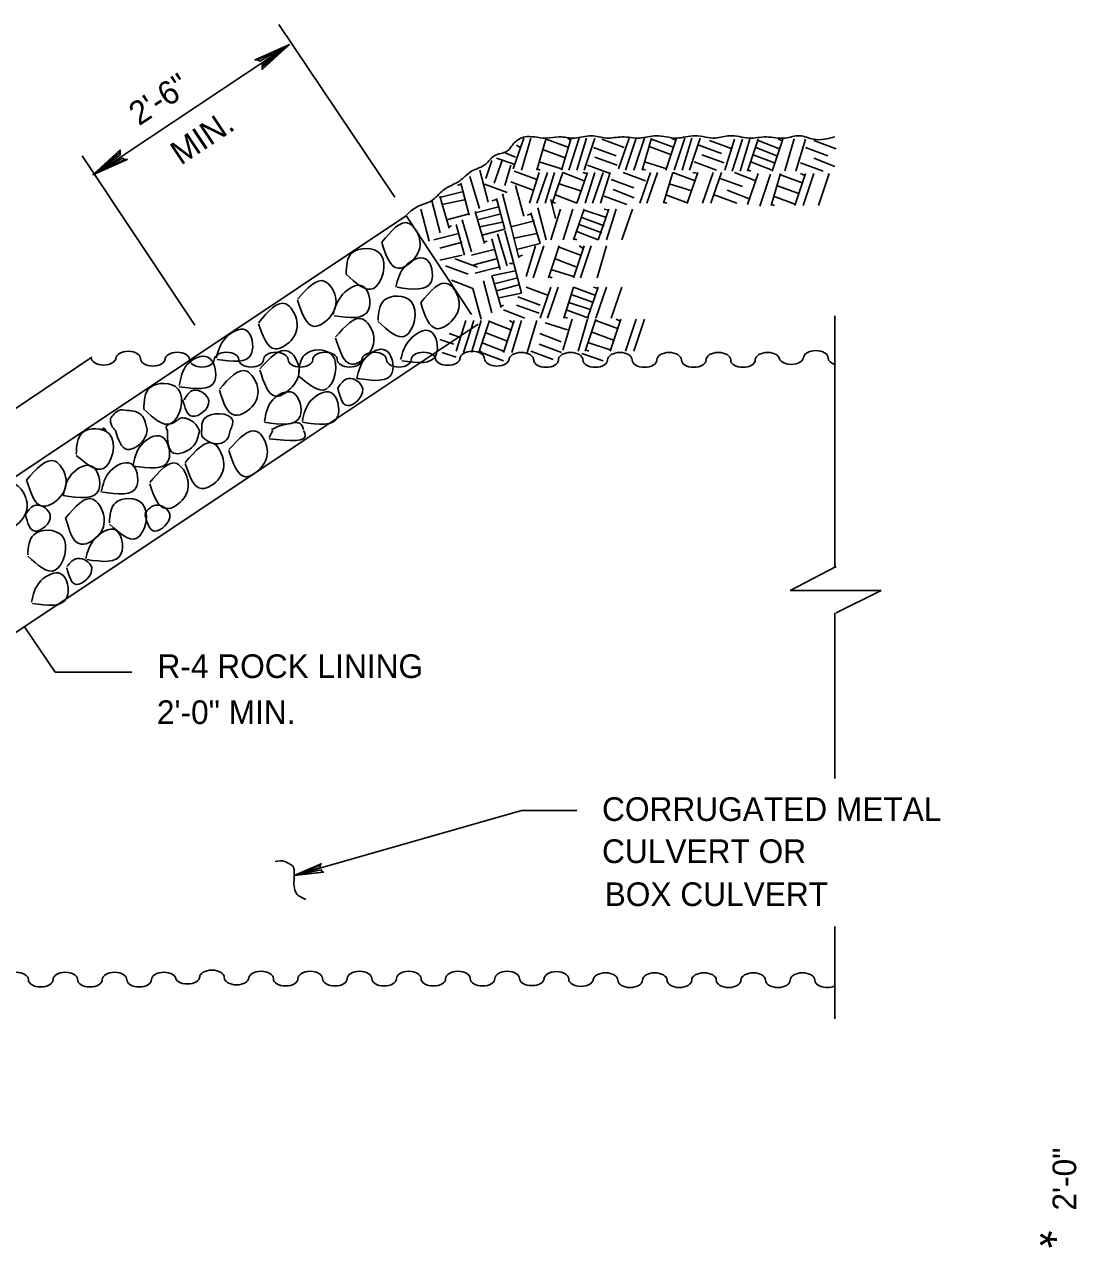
# Model space of a CAD drawing. Extents: x 639011 to 639866, y 298840 to 300028.
# Drawn here: x 639264.7 to 639398.1, y 298970.3 to 299125.2 of the extents above; entities that cross this region are included whole.
import ezdxf

# ---------------------------------------------------------------- set-up
doc = ezdxf.new("R2010")
doc.units = 0
doc.layers.add('2', color=7, linetype='Continuous')

msp = doc.modelspace()

# ---------------------------------------------------------------- linework, layer by layer
at = {"layer": '2'}
for p, q in [((639311.64, 299103.35), (639296.94, 299125.25)), ((639273.61, 299106.24), (639298.29, 299122.7)), ((639327.99, 299110.85), (639326.64, 299106.95)), ((639328.89, 299110.85), (639327.69, 299106.8)), ((639330.84, 299110.85), (639329.64, 299106.8)), ((639333.69, 299109.65), (639330.84, 299110.7)), ((639333.99, 299110.85), (639332.79, 299106.8)), ((639333.99, 299110.55), (639333.54, 299110.85)), ((639335.04, 299110.85), (639333.69, 299106.8)), ((639335.94, 299110.85), (639334.74, 299106.8)), ((639336.99, 299110.85), (639335.64, 299106.8)), ((639340.74, 299109.65), (639337.89, 299110.7)), ((639341.34, 299110.85), (639339.99, 299106.95)), ((639342.24, 299110.85), (639340.89, 299106.8)), ((639343.29, 299110.85), (639341.94, 299106.8)), ((639344.19, 299110.85), (639342.99, 299106.8)), ((639347.04, 299109.65), (639344.19, 299110.7)), ((639347.34, 299110.85), (639345.99, 299106.8)), ((639347.34, 299110.55), (639346.74, 299110.85)), ((639348.39, 299110.85), (639347.04, 299106.8)), ((639349.29, 299110.85), (639348.09, 299106.8)), ((639350.34, 299110.85), (639348.99, 299106.8)), ((639354.39, 299109.5), (639351.54, 299110.55)), ((639354.69, 299110.7), (639353.49, 299106.8)), ((639355.74, 299110.7), (639354.39, 299106.65)), ((639356.64, 299110.7), (639355.44, 299106.65)), ((639357.69, 299110.7), (639356.34, 299106.65)), ((639360.39, 299109.5), (639357.69, 299110.55)), ((639360.84, 299110.7), (639359.49, 299106.65)), ((639360.69, 299110.55), (639360.24, 299110.7)), ((639362.28, 299110.77), (639361.08, 299106.72)), ((639363.69, 299110.7), (639362.49, 299106.65)), ((639367.59, 299109.5), (639364.74, 299110.55)), ((639286.29, 299087.15), (639272.04, 299108.6)), ((639326.94, 299108.45), (639325.44, 299109.05)), ((639327.54, 299109.65), (639327.09, 299109.95)), ((639333.24, 299108.36), (639330.39, 299109.41)), ((639339.69, 299108.6), (639336.84, 299109.65)), ((639346.74, 299108.75), (639343.89, 299109.8)), ((639353.04, 299108.9), (639350.19, 299109.95)), ((639353.4, 299107.7), (639350.55, 299108.75)), ((639359.79, 299107.7), (639357.09, 299108.75)), ((639360.09, 299108.6), (639357.39, 299109.65)), ((639366.54, 299108.6), (639363.69, 299109.65)), ((639323.94, 299108), (639323.19, 299105.75)), ((639325.29, 299108.15), (639324.24, 299105.15)), ((639326.79, 299107.55), (639324.54, 299108.3)), ((639326.34, 299107.4), (639325.59, 299104.85)), ((639332.79, 299106.95), (639329.94, 299107.85)), ((639338.94, 299106.35), (639336.09, 299107.4)), ((639339.84, 299107.4), (639336.99, 299108.45)), ((639346.14, 299106.95), (639343.29, 299107.85)), ((639352.44, 299106.8), (639349.59, 299107.85)), ((639359.49, 299106.8), (639356.79, 299107.85)), ((639365.94, 299106.65), (639363.09, 299107.7)), ((639367.44, 299107.25), (639364.74, 299108.3)), ((639321.18, 299105.98), (639322.38, 299101.93)), ((639322.44, 299106.8), (639323.49, 299102.75)), ((639329.64, 299105.6), (639326.79, 299106.65)), ((639329.94, 299106.5), (639328.74, 299102.6)), ((639330.09, 299106.8), (639329.64, 299106.95)), ((639330.99, 299106.5), (639329.64, 299102.6)), ((639331.89, 299106.5), (639330.69, 299102.6)), ((639332.94, 299106.5), (639331.59, 299102.6)), ((639335.64, 299105.45), (639332.94, 299106.5)), ((639336.09, 299106.5), (639334.74, 299102.6)), ((639335.94, 299106.35), (639335.49, 299106.5)), ((639336.99, 299106.5), (639335.79, 299102.6)), ((639338.04, 299106.5), (639336.69, 299102.6)), ((639338.94, 299106.5), (639337.74, 299102.6)), ((639341.94, 299104.55), (639339.09, 299105.6)), ((639343.44, 299105.45), (639340.59, 299106.5)), ((639344.04, 299106.5), (639342.69, 299102.6)), ((639343.44, 299106.8), (639342.99, 299106.95)), ((639344.94, 299106.5), (639343.59, 299102.6)), ((639346.89, 299106.5), (639345.69, 299102.6)), ((639349.74, 299105.45), (639346.89, 299106.5)), ((639350.04, 299106.5), (639348.69, 299102.6)), ((639350.04, 299106.35), (639349.44, 299106.5)), ((639351.99, 299106.5), (639350.64, 299102.6)), ((639353.04, 299106.5), (639351.69, 299102.6)), ((639355.74, 299104.7), (639352.89, 299105.75)), ((639357.39, 299105.45), (639354.69, 299106.5)), ((639357.69, 299106.35), (639356.34, 299102.45)), ((639356.79, 299106.65), (639356.49, 299106.8)), ((639359.25, 299106.27), (639357.9, 299102.22)), ((639360.54, 299106.35), (639359.34, 299102.3)), ((639363.39, 299105.15), (639360.54, 299106.2)), ((639363.69, 299106.35), (639362.34, 299102.3)), ((639363.69, 299106.05), (639363.09, 299106.35)), ((639364.74, 299106.35), (639363.39, 299102.3)), ((639366.69, 299106.35), (639365.34, 299102.3)), ((639320.34, 299104.1), (639317.49, 299103.35)), ((639320.04, 299105), (639319.59, 299104.85)), ((639320.04, 299105.15), (639321.09, 299101.1)), ((639325.89, 299103.95), (639323.04, 299105)), ((639329.19, 299104.25), (639326.34, 299105.3)), ((639326.94, 299104.85), (639327.99, 299100.95)), ((639335.19, 299104.16), (639332.49, 299105.06)), ((639342.01, 299103.28), (639339.31, 299104.33)), ((639349.29, 299104.16), (639346.44, 299105.06)), ((639356.49, 299103.2), (639353.79, 299104.25)), ((639362.87, 299103.81), (639360.02, 299104.86)), ((639316.36, 299102.9), (639317.41, 299098.85)), ((639317.34, 299103.5), (639318.54, 299099.45)), ((639320.64, 299103.05), (639317.64, 299102.45)), ((639324.54, 299103.05), (639323.94, 299102.9)), ((639324.54, 299103.2), (639325.59, 299099.3)), ((639325.29, 299103.8), (639326.34, 299099.75)), ((639331.44, 299103.05), (639332.04, 299100.65)), ((639332.04, 299102.6), (639331.74, 299102.75)), ((639334.74, 299102.6), (639332.04, 299103.65)), ((639341.04, 299102.45), (639338.19, 299103.5)), ((639346.14, 299102.6), (639345.69, 299102.75)), ((639348.84, 299102.6), (639345.99, 299103.65)), ((639354.99, 299102.6), (639352.14, 299103.65)), ((639359.79, 299102.3), (639359.34, 299102.45)), ((639362.49, 299102.45), (639359.64, 299103.5)), ((639272.34, 299073.8), (639312.99, 299100.95)), ((639321.39, 299088.5), (639313.14, 299100.95)), ((639314.94, 299101.85), (639315.99, 299097.8)), ((639321.09, 299101.25), (639318.24, 299100.5)), ((639324.84, 299102.15), (639321.84, 299101.4)), ((639321.84, 299101.55), (639323.04, 299097.5)), ((639325.14, 299101.25), (639322.14, 299100.5)), ((639329.04, 299101.25), (639328.44, 299101.1)), ((639328.89, 299101.4), (639330.09, 299097.5)), ((639329.79, 299102), (639330.84, 299097.95)), ((639332.64, 299101.85), (639331.44, 299097.95)), ((639334.2, 299101.85), (639333, 299097.95)), ((639335.64, 299101.85), (639334.29, 299097.95)), ((639338.19, 299099.75), (639335.34, 299100.8)), ((639338.49, 299100.8), (639335.64, 299101.7)), ((639338.79, 299101.85), (639337.44, 299097.95)), ((639338.79, 299101.7), (639338.19, 299101.85)), ((639339.69, 299101.85), (639338.49, 299097.95)), ((639341.79, 299101.85), (639340.44, 299097.95)), ((639318.84, 299099.75), (639318.54, 299099.6)), ((639319.44, 299099.9), (639320.49, 299096)), ((639320.19, 299100.5), (639321.39, 299096.45)), ((639325.29, 299100.2), (639322.44, 299099.6)), ((639325.59, 299099.3), (639322.74, 299098.55)), ((639329.34, 299100.35), (639326.34, 299099.6)), ((639326.34, 299099.75), (639327.39, 299095.7)), ((639337.89, 299098.85), (639335.04, 299099.9)), ((639319.59, 299098.7), (639316.59, 299097.95)), ((639323.34, 299097.8), (639322.89, 299097.65)), ((639323.94, 299098.1), (639324.99, 299094.2)), ((639324.69, 299098.7), (639325.89, 299094.65)), ((639325.59, 299099.15), (639326.64, 299095.25)), ((639329.64, 299098.78), (639326.79, 299098.18)), ((639334.74, 299097.95), (639334.44, 299098.1)), ((639337.44, 299097.95), (639334.74, 299099)), ((639320.19, 299097.65), (639317.34, 299096.9)), ((639324.24, 299096.75), (639321.39, 299096)), ((639330.09, 299097.5), (639327.09, 299096.75)), ((639329.49, 299097.2), (639328.29, 299093.3)), ((639330.54, 299097.2), (639329.19, 299093.15)), ((639332.49, 299097.2), (639331.14, 299093.15)), ((639335.19, 299096), (639332.49, 299097.05)), ((639335.64, 299097.2), (639334.29, 299093.15)), ((639335.49, 299096.9), (639335.04, 299097.2)), ((639336.54, 299097.2), (639335.19, 299093.15)), ((639338.49, 299097.2), (639337.29, 299093.15)), ((639320.19, 299096), (639317.34, 299095.4)), ((639320.94, 299093.6), (639318.09, 299094.65)), ((639322.14, 299094.5), (639319.29, 299095.55)), ((639324.54, 299095.55), (639321.69, 299094.8)), ((639326.64, 299094.95), (639326.19, 299094.95)), ((639326.64, 299095.25), (639327.69, 299091.2)), ((639327.84, 299096), (639327.39, 299095.85)), ((639334.58, 299094.56), (639331.88, 299095.61)), ((639324.84, 299094.5), (639321.84, 299093.75)), ((639323.94, 299093.45), (639325.14, 299089.4)), ((639326.94, 299094.05), (639324.09, 299093.45)), ((639327.24, 299093.15), (639324.24, 299092.4)), ((639331.59, 299093.15), (639331.14, 299093.3)), ((639334.29, 299093.3), (639331.44, 299094.2)), ((639321.54, 299091.8), (639318.84, 299092.85)), ((639321.54, 299091.8), (639322.59, 299087.9)), ((639322.88, 299092.77), (639323.93, 299088.72)), ((639327.39, 299092.25), (639324.54, 299091.5)), ((639331.14, 299090.9), (639328.29, 299091.95)), ((639331.44, 299091.95), (639330.09, 299088.05)), ((639332.34, 299091.95), (639330.99, 299088.05)), ((639334.29, 299091.95), (639333.09, 299088.05)), ((639337.14, 299090.9), (639334.29, 299091.95)), ((639337.44, 299091.95), (639336.09, 299088.05)), ((639337.44, 299091.8), (639336.84, 299091.95)), ((639338.49, 299091.95), (639337.14, 299088.05)), ((639340.44, 299091.95), (639339.09, 299088.05)), ((639327.69, 299091.2), (639324.84, 299090.6)), ((639330.09, 299089.7), (639327.24, 299090.75)), ((639336.54, 299089.1), (639333.69, 299090)), ((639336.84, 299090), (639333.99, 299091.05)), ((639325.44, 299089.7), (639325.14, 299089.55)), ((639328.14, 299088.05), (639325.44, 299089.1)), ((639329.94, 299088.65), (639327.09, 299089.7)), ((639336.24, 299088.05), (639333.39, 299089.1)), ((639300.15, 299072.58), (639322.2, 299087.28)), ((639320.64, 299087.75), (639319.44, 299083.85)), ((639321.69, 299087.75), (639320.34, 299083.7)), ((639322.59, 299087.75), (639321.39, 299083.7)), ((639323.64, 299087.75), (639322.29, 299083.7)), ((639326.34, 299086.55), (639323.64, 299087.6)), ((639326.79, 299087.75), (639325.44, 299083.7)), ((639326.64, 299087.45), (639326.19, 299087.75)), ((639327.69, 299087.75), (639326.49, 299083.7)), ((639329.64, 299087.75), (639328.44, 299083.7)), ((639333.54, 299086.55), (639330.69, 299087.45)), ((639334.14, 299087.9), (639332.94, 299084)), ((639333.54, 299088.05), (639333.09, 299088.2)), ((639336.09, 299087.9), (639334.89, 299083.85)), ((639337.14, 299087.9), (639335.79, 299083.85)), ((639339.99, 299086.7), (639337.14, 299087.75)), ((639340.29, 299087.9), (639338.94, 299083.85)), ((639340.29, 299087.6), (639339.69, 299087.9)), ((639342.24, 299087.9), (639340.89, 299083.85)), ((639343.29, 299087.9), (639341.94, 299083.85)), ((639367.44, 299056.4), (639367.44, 299088.35)), ((639319.14, 299084.75), (639317.34, 299085.35)), ((639319.74, 299085.65), (639318.54, 299086.1)), ((639325.81, 299085.18), (639323.11, 299086.23)), ((639332.73, 299085.04), (639330.03, 299086.09)), ((639339.38, 299085.26), (639336.53, 299086.31)), ((639322.74, 299083.7), (639322.44, 299083.85)), ((639325.44, 299083.85), (639322.74, 299084.9)), ((639331.74, 299082.8), (639328.89, 299083.85)), ((639332.79, 299083.7), (639329.94, 299084.75)), ((639336.24, 299083.85), (639335.94, 299084)), ((639339.09, 299084), (639336.24, 299084.9)), ((639259.44, 299073.8), (639273.24, 299083.1)), ((639319.44, 299083.1), (639317.64, 299083.7)), ((639325.44, 299082.65), (639322.59, 299083.7)), ((639338.04, 299082.65), (639335.34, 299083.55)), ((639211.44, 299033.15), (639272.34, 299073.8)), ((639295.74, 299072.9), (639296.19, 299073.8)), ((639212.25, 299013.93), (639300.15, 299072.58)), ((639361.74, 299053.55), (639367.59, 299056.55)), ((639361.74, 299053.55), (639373.29, 299053.55)), ((639373.29, 299053.55), (639367.59, 299050.7)), ((639367.44, 299029.7), (639367.44, 299050.7)), ((639264.72, 299048.94), (639268.59, 299043.2)), ((639268.59, 299043.2), (639278.34, 299043.2)), ((639298.89, 299017.4), (639327.69, 299025.65)), ((639327.69, 299025.65), (639334.74, 299025.65)), ((639367.44, 298999.25), (639367.44, 299010.95))]:
    msp.add_line(p, q, dxfattribs=at)
for points in [[(639294.24, 299120.75), (639294.54, 299120.6), (639298.29, 299122.7), (639294.24, 299120.75), (639293.94, 299120.75), (639298.29, 299122.7), (639294.84, 299120.15), (639294.84, 299119.85), (639298.29, 299122.7), (639294.84, 299119.55), (639294.84, 299119.85)], [(639277.44, 299108.15), (639277.14, 299108.3), (639273.39, 299106.2), (639277.44, 299108.15), (639277.74, 299108.15), (639273.39, 299106.2), (639276.84, 299108.75), (639276.84, 299109.05), (639273.39, 299106.2), (639276.84, 299109.35), (639276.84, 299109.05)], [(639302.49, 299017.85), (639302.34, 299018.15), (639298.89, 299017.4), (639302.49, 299017.85), (639302.64, 299017.85), (639298.89, 299017.4), (639302.19, 299018.45), (639302.19, 299018.75), (639298.89, 299017.4), (639302.34, 299018.9), (639302.19, 299018.75)]]:
    msp.add_lwpolyline(points, dxfattribs=at)
for centre, major_axis, end_param in [((639277.87, 299082.91), (-1.56, 0), 6.283185), ((639321.47, 299082.9), (-1.56, 0), 6.283185), ((639365.01, 299083), (-1.56, 0), 6.283185), ((639274.75, 299083.02), (1.56, 0), 6.283185), ((639280.99, 299082.91), (1.56, 0), 6.283185), ((639284.09, 299082.77), (-1.56, 0), 6.283185), ((639287.21, 299082.77), (1.56, 0), 6.283185), ((639290.33, 299082.77), (-1.56, 0), 6.283185), ((639293.45, 299082.77), (1.56, 0), 6.283185), ((639296.57, 299082.77), (-1.56, 0), 6.283185), ((639299.69, 299082.77), (1.56, 0), 6.283185), ((639302.81, 299082.77), (-1.56, 0), 6.283185), ((639305.93, 299082.77), (1.56, 0), 6.283185), ((639309.05, 299082.77), (-1.56, 0), 6.283185), ((639312.17, 299082.77), (1.56, 0), 6.283185), ((639315.29, 299082.77), (-1.56, 0), 6.283185), ((639318.36, 299083), (1.56, 0), 6.283185), ((639318.41, 299082.83), (1.56, 0), 3.221678), ((639324.59, 299082.9), (1.56, 0), 6.283185), ((639327.69, 299082.75), (-1.56, 0), 6.283185), ((639330.82, 299082.75), (1.56, 0), 6.283185), ((639333.94, 299082.75), (-1.56, 0), 6.283185), ((639337.06, 299082.75), (1.56, 0), 6.283185), ((639340.18, 299082.75), (-1.56, 0), 6.283185), ((639343.3, 299082.75), (1.56, 0), 6.283185), ((639346.42, 299082.75), (-1.56, 0), 6.283185), ((639349.54, 299082.75), (1.56, 0), 6.283185), ((639352.66, 299082.75), (-1.56, 0), 6.283185), ((639355.78, 299082.75), (1.56, 0), 6.283185), ((639358.9, 299082.75), (-1.56, 0), 6.283185), ((639361.9, 299083.11), (1.56, 0), 6.283185), ((639362.01, 299082.81), (1.56, 0), 3.221678), ((639368.13, 299083), (1.56, 0), 4.303178), ((639263.66, 299004.23), (-1.56, 0), 6.283185), ((639269.9, 299004.23), (-1.56, 0), 6.283185), ((639276.14, 299004.23), (-1.56, 0), 6.283185), ((639282.38, 299004.23), (-1.56, 0), 6.283185), ((639288.48, 299004.5), (-1.56, 0), 6.283185), ((639294.7, 299004.36), (-1.56, 0), 6.283185), ((639300.94, 299004.36), (-1.56, 0), 6.283185), ((639307.18, 299004.36), (-1.56, 0), 6.283185), ((639313.42, 299004.36), (-1.56, 0), 6.283185), ((639319.66, 299004.36), (-1.56, 0), 6.283185), ((639325.9, 299004.36), (-1.56, 0), 6.283185), ((639332.13, 299004.3), (-1.56, 0), 6.283185), ((639338.36, 299004.16), (-1.56, 0), 6.283185), ((639344.6, 299004.16), (-1.56, 0), 6.283185), ((639350.84, 299004.16), (-1.56, 0), 6.283185), ((639357.08, 299004.16), (-1.56, 0), 6.283185), ((639363.32, 299004.16), (-1.56, 0), 6.283185), ((639266.78, 299004.23), (1.56, 0), 6.283185), ((639273.02, 299004.23), (1.56, 0), 6.283185), ((639279.26, 299004.23), (1.56, 0), 6.283185), ((639285.37, 299004.61), (1.56, 0), 6.283185), ((639285.5, 299004.29), (1.56, 0), 3.221678), ((639291.6, 299004.5), (1.56, 0), 6.283185), ((639297.82, 299004.36), (1.56, 0), 6.283185), ((639304.06, 299004.36), (1.56, 0), 6.283185), ((639310.3, 299004.36), (1.56, 0), 6.283185), ((639316.54, 299004.36), (1.56, 0), 6.283185), ((639322.78, 299004.36), (1.56, 0), 6.283185), ((639329.02, 299004.42), (1.56, 0), 3.221678), ((639329.02, 299004.4), (1.56, 0), 6.283185), ((639335.25, 299004.3), (1.56, 0), 6.283185), ((639341.48, 299004.16), (1.56, 0), 6.283185), ((639347.72, 299004.16), (1.56, 0), 6.283185), ((639353.96, 299004.16), (1.56, 0), 6.283185), ((639360.2, 299004.16), (1.56, 0), 6.283185), ((639366.44, 299004.16), (1.56, 0), 5.472402)]:
    msp.add_ellipse(centre, major_axis=major_axis, ratio=0.6, start_param=3.141593, end_param=end_param, dxfattribs=at)
for points in [[(639312.99, 299100.95), (639314.49, 299102.15), (639316.29, 299102.9), (639317.79, 299104.25), (639319.89, 299105.45), (639321.39, 299106.65), (639323.19, 299107.55), (639324.24, 299108.6), (639325.89, 299109.2), (639326.79, 299110.25), (639328.14, 299111), (639329.34, 299111), (639330.84, 299110.85), (639332.49, 299111), (639334.44, 299110.85), (639336.54, 299111.15), (639338.49, 299110.85), (639340.44, 299111), (639342.69, 299110.85), (639344.79, 299111.15), (639347.34, 299110.85), (639349.74, 299111.15), (639352.29, 299110.85), (639354.09, 299111.15), (639356.49, 299110.85), (639358.74, 299111), (639361.14, 299110.85), (639362.94, 299111.15), (639364.74, 299110.7), (639367.44, 299111)], [(639309.99, 299097.65), (639313.44, 299100.05), (639314.79, 299098.1), (639314.34, 299095.85), (639312.09, 299094.35), (639309.99, 299097.65)], [(639305.49, 299093.6), (639306.24, 299096.3), (639309.84, 299096.15), (639308.94, 299091.8), (639305.49, 299093.6)], [(639311.79, 299091.95), (639312.99, 299094.65), (639315.54, 299095.55), (639316.29, 299092.7), (639311.94, 299091.95)], [(639299.34, 299090.45), (639302.79, 299092.7), (639304.14, 299090.75), (639303.69, 299088.5), (639301.44, 299087), (639299.34, 299090.3)], [(639303.84, 299088.5), (639305.04, 299091.05), (639307.59, 299092.1), (639308.34, 299089.1), (639303.99, 299088.35)], [(639314.94, 299090), (639318.39, 299092.4), (639319.74, 299090.45), (639319.29, 299088.2), (639317.04, 299086.7), (639314.94, 299090)], [(639294.39, 299087.45), (639297.84, 299089.85), (639299.19, 299087.9), (639298.74, 299085.5), (639296.49, 299084.15), (639294.39, 299087.3)], [(639309.54, 299087.75), (639310.29, 299090.3), (639313.74, 299090.15), (639312.99, 299085.8), (639309.54, 299087.6)], [(639288.99, 299082.95), (639290.19, 299085.5), (639292.74, 299086.55), (639293.49, 299083.55), (639289.14, 299082.8)], [(639304.14, 299085.65), (639307.59, 299087.9), (639308.94, 299085.95), (639308.49, 299083.7), (639306.24, 299082.2), (639304.14, 299085.5)], [(639312.39, 299082.8), (639313.59, 299085.35), (639316.14, 299086.4), (639316.89, 299083.4), (639312.54, 299082.65)], [(639294.54, 299081.6), (639298.14, 299083.85), (639299.49, 299081.9), (639298.89, 299079.65), (639296.64, 299078.15), (639294.54, 299081.45)], [(639299.49, 299080.85), (639300.24, 299083.4), (639303.69, 299083.4), (639302.94, 299079.05), (639299.49, 299080.7)], [(639306.84, 299080.4), (639308.04, 299083.1), (639310.44, 299084), (639311.34, 299081.15), (639306.84, 299080.4)], [(639284.34, 299079.5), (639285.39, 299082.2), (639287.94, 299083.1), (639288.84, 299080.1), (639284.34, 299079.35)], [(639289.44, 299079.05), (639292.89, 299081.3), (639294.24, 299079.35), (639293.79, 299077.1), (639291.39, 299075.75), (639289.44, 299078.9)], [(639279.84, 299076.5), (639280.59, 299079.2), (639284.19, 299079.05), (639283.29, 299074.7), (639279.84, 299076.5)], [(639304.44, 299079.2), (639305.79, 299080.4), (639307.59, 299079.05), (639305.64, 299076.95), (639304.44, 299079.2)], [(639284.94, 299077.7), (639286.14, 299078.9), (639288.09, 299077.55), (639285.99, 299075.6), (639284.79, 299077.7)], [(639295.14, 299075), (639296.19, 299077.7), (639298.74, 299078.6), (639299.64, 299075.6), (639295.14, 299074.85)], [(639299.94, 299075), (639300.99, 299077.55), (639303.54, 299078.6), (639304.44, 299075.6), (639299.94, 299074.85)], [(639280.29, 299073.8), (639280.14, 299074.4), (639279.69, 299075.6), (639278.79, 299076.2), (639277.74, 299076.35), (639276.69, 299076.35), (639276.09, 299075.9), (639275.64, 299075.3), (639275.79, 299074.4), (639276.24, 299073.8)], [(639287.19, 299073.8), (639287.49, 299075.3), (639291.09, 299075.15), (639290.79, 299073.8)], [(639286.89, 299073.8), (639286.44, 299074.55), (639285.69, 299075.15), (639284.34, 299075.3), (639283.74, 299074.85), (639282.69, 299074.25), (639282.84, 299073.8)], [(639300.09, 299073.95), (639299.64, 299074.7), (639298.44, 299074.7), (639297.09, 299074.4), (639296.04, 299073.95)], [(639271.29, 299070.8), (639272.04, 299073.5), (639275.49, 299073.35), (639274.74, 299069), (639271.29, 299070.65)], [(639274.44, 299073.8), (639274.74, 299074.1), (639275.04, 299073.8)], [(639280.29, 299073.8), (639279.99, 299072.9), (639277.74, 299071.4), (639276.24, 299073.8)], [(639278.49, 299069.3), (639279.54, 299072), (639282.09, 299073.05), (639282.99, 299070.05), (639278.49, 299069.3)], [(639286.89, 299073.8), (639286.14, 299071.85), (639283.59, 299070.95), (639282.84, 299073.8)], [(639287.19, 299073.95), (639287.19, 299073.2), (639287.94, 299072.45), (639289.44, 299072.15), (639290.34, 299072.6), (639290.79, 299073.8)], [(639290.64, 299071.4), (639294.24, 299073.65), (639295.44, 299071.7), (639294.99, 299069.45), (639292.74, 299067.95), (639290.64, 299071.25)], [(639300.09, 299073.8), (639300.24, 299073.5), (639295.74, 299072.75)], [(639285.09, 299069.75), (639288.69, 299072.15), (639289.89, 299070.2), (639289.44, 299067.8), (639287.19, 299066.45), (639285.09, 299069.6)], [(639264.99, 299067.5), (639268.59, 299069.9), (639269.94, 299067.95), (639269.49, 299065.7), (639267.09, 299064.2), (639264.99, 299067.5)], [(639274.44, 299066), (639275.64, 299068.7), (639278.19, 299069.6), (639278.94, 299066.75), (639274.59, 299066)], [(639280.59, 299067.2), (639284.04, 299069.6), (639285.39, 299067.65), (639284.94, 299065.25), (639282.69, 299063.9), (639280.59, 299067.05)], [(639269.64, 299065.55), (639270.69, 299068.25), (639273.24, 299069.3), (639274.14, 299066.3), (639269.64, 299065.55)], [(639260.04, 299064.65), (639263.64, 299066.9), (639264.99, 299064.95), (639264.54, 299062.7), (639262.14, 299061.2), (639260.04, 299064.5)], [(639269.94, 299062.7), (639273.39, 299065.1), (639274.74, 299063.15), (639274.29, 299060.75), (639271.89, 299059.4), (639269.94, 299062.7)], [(639275.49, 299062.1), (639276.24, 299064.65), (639279.69, 299064.5), (639278.94, 299060.15), (639275.49, 299061.95)], [(639264.84, 299063.15), (639266.19, 299064.35), (639267.99, 299063), (639266.04, 299061.05), (639264.84, 299063.15)], [(639279.99, 299063.3), (639281.34, 299064.35), (639283.14, 299063.15), (639281.19, 299061.05), (639279.99, 299063.15)], [(639265.14, 299058.05), (639265.89, 299060.6), (639269.49, 299060.45), (639268.59, 299056.1), (639265.14, 299057.9)], [(639272.49, 299057.6), (639273.69, 299060.15), (639276.24, 299061.2), (639276.99, 299058.2), (639272.64, 299057.45)], [(639270.09, 299056.55), (639271.44, 299057.6), (639273.24, 299056.4), (639271.29, 299054.3), (639270.09, 299056.4)], [(639265.59, 299052.05), (639266.79, 299054.75), (639269.34, 299055.65), (639270.09, 299052.65), (639265.74, 299051.9)], [(639296.49, 299019.2), (639297.69, 299019.2), (639298.29, 299018.9), (639298.74, 299018.6), (639298.89, 299018), (639298.89, 299017.1), (639298.89, 299016.05), (639299.19, 299015.15), (639300.39, 299014.4)]]:
    msp.add_spline(points, degree=3, dxfattribs=at)

# ---------------------------------------------------------------- texts
for s, height, rotation, p in [('2\'-6"', 3, 33.6901, (639279.25, 299112.33)), ('MIN.', 3, 33.6901, (639284.54, 299107.34)), ('2\'-0"', 3, 90, (639398.01, 298974.96)), ('*', 4.32, 270, (639391.25, 298972.44))]:
    msp.add_text(s, height=height, rotation=rotation, dxfattribs=at).set_placement(p)
for s, height, p in [('R-4 ROCK LINING', 2.9999, (639281.58, 299042.44)), ('2\'-0" MIN.', 3, (639281.5, 299036.61)), ('CORRUGATED METAL', 2.9999, (639337.92, 299024.33)), ('CULVERT OR', 3, (639337.92, 299019)), ('BOX CULVERT', 2.9999, (639338.25, 299013.55))]:
    msp.add_text(s, height=height, dxfattribs=at).set_placement(p)

doc.saveas('drawing.dxf')
